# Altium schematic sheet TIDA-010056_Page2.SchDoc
size 431 x 279 mm; Date: Not shown in title block; ApprovedBy: Not shown in title block; CheckedBy: Not shown in title block; Author: Not shown in title block; CompanyName: Not shown in title block; DrawnBy: Manu; Engineer: Not shown in title block; Organization: Not shown in title block; Address1: Not shown in title block; Address2: Not shown in title block; Address3: Not shown in title block; Address4: Not shown in title block; DocumentNumber: 1; Revision: Use project parameter SCH_Rev; SheetNumber: 3; SheetTotal: 5; PageSetup: Record=PageOptions¦CenterHorizontal=True¦CenterVertical=True¦PrintScale=1.00¦XCorrection=1.00¦YCorrection=1.00¦PrintKind=0¦BorderSize=5000000¦LeftOffset=0¦BottomOffset=0¦Orientation=2¦PaperLength=1000¦PaperWidth=1000¦Scale=100¦PaperSource=15¦PrintQuality=600¦MediaType=1¦DitherType=10¦PaperKind=Letter¦PrintScaleMode=1
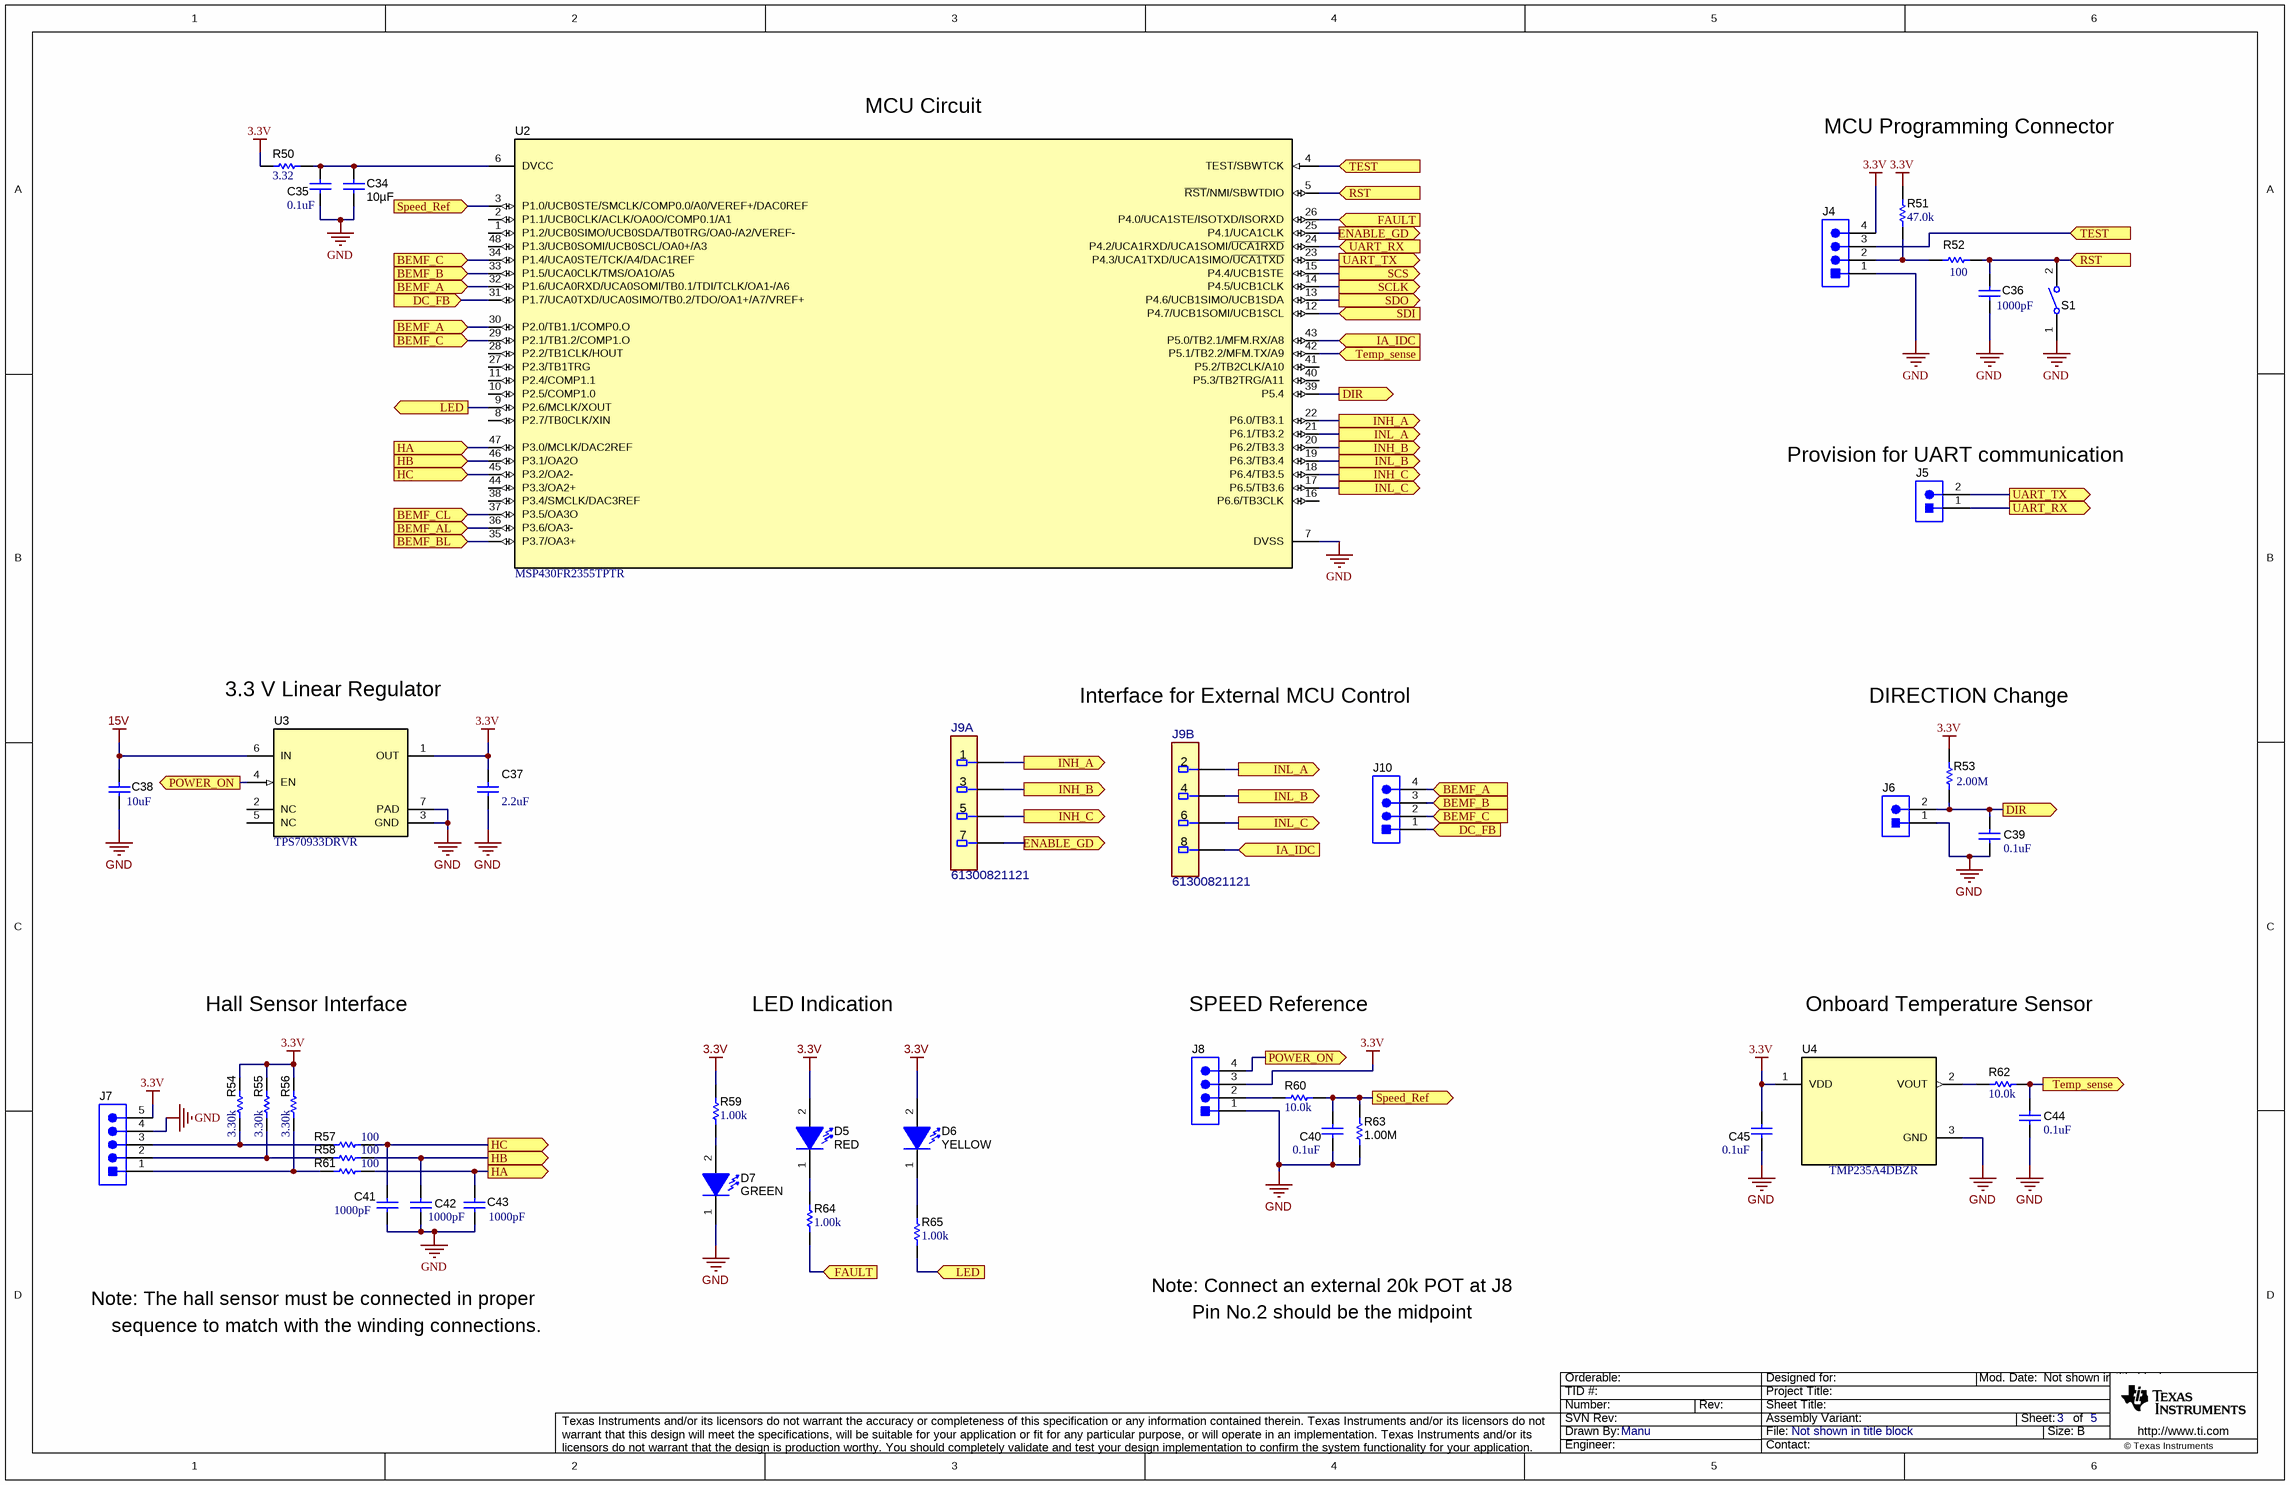
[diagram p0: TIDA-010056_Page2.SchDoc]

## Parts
C34  ValueDisplayed: 10µF  [0603]  (hidden comment: GRM188R61A106KE69D)
C35  ValueDisplayed: 0.1uF  [0402]  (hidden comment: GCM155R71A104KA55D)
C36  ValueDisplayed: 1000pF  [0402]  (hidden comment: GRM155R71C102KA01D)
C37  ValueDisplayed: 2.2uF  [0402]  (hidden comment: 885012105013)
C38  ValueDisplayed: 10uF  [1206_190]  (hidden comment: C3216X7R1V106M160AC)
C39  ValueDisplayed: 0.1uF  [0402]  (hidden comment: GCM155R71A104KA55D)
C40  ValueDisplayed: 0.1uF  [0402]  (hidden comment: GCM155R71A104KA55D)
C41  ValueDisplayed: 1000pF  [0402]  (hidden comment: GRM155R71C102KA01D)
C42  ValueDisplayed: 1000pF  [0402]  (hidden comment: GRM155R71C102KA01D)
C43  ValueDisplayed: 1000pF  [0402]  (hidden comment: GRM155R71C102KA01D)
C44  ValueDisplayed: 0.1uF  [0402]  (hidden comment: GCM155R71A104KA55D)
C45  ValueDisplayed: 0.1uF  [0402]  (hidden comment: GCM155R71A104KA55D)
D5  value RED  [WL-SMCW_GREEN]  (hidden comment: 150060GS75000)
D6  value YELLOW  [WL-SMCW_GREEN]  (hidden comment: 150060GS75000)
D7  value GREEN  [WL-SMCW_GREEN]  (hidden comment: 150060GS75000)
J4  61300411121  [WURTH_61300411121]  (value not drawn)
J5  61300211121  [WURTH_61300211121]  (value not drawn)
J6  61300211121  [WURTH_61300211121]  (value not drawn)
J7  61300511121  [Wurth_61300511121]  (value not drawn)
J8  61300411121  [WURTH_61300411121]  (value not drawn)
J9  61300821121  [FP-61300821121_HDR8-MFG]  (parts A,B of 2)
J10  61300411121  [WURTH_61300411121]  (value not drawn)
R50  ValueDisplayed: 3.32  [0402]  (hidden comment: CRCW04023R32FKED)
R51  ValueDisplayed: 47.0k  [0402]  (hidden comment: RC0402FR-0747KL)
R52  ValueDisplayed: 100  [0402]  (hidden comment: ERJ-2GEJ101X)
R53  ValueDisplayed: 2.00M  [0402]  (hidden comment: CRCW04022M00FKED)
R54  ValueDisplayed: 3.30k  [0402]  (hidden comment: ERJ-2RKF3301X)
R55  ValueDisplayed: 3.30k  [0402]  (hidden comment: ERJ-2RKF3301X)
R56  ValueDisplayed: 3.30k  [0402]  (hidden comment: ERJ-2RKF3301X)
R57  ValueDisplayed: 100  [0402]  (hidden comment: ERJ-2GEJ101X)
R58  ValueDisplayed: 100  [0402]  (hidden comment: ERJ-2GEJ101X)
R59  ValueDisplayed: 1.00k  [0402]  (hidden comment: ERJ-2RKF1001X)
R60  ValueDisplayed: 10.0k  [0402]  (hidden comment: ERJ-2RKF1002X)
R61  ValueDisplayed: 100  [0402]  (hidden comment: ERJ-2GEJ101X)
R62  ValueDisplayed: 10.0k  [0402]  (hidden comment: ERJ-2RKF1002X)
R63  ValueDisplayed: 1.00M  [0402]  (hidden comment: ERJ-2RKF1004X)
R64  ValueDisplayed: 1.00k  [0402]  (hidden comment: ERJ-2RKF1001X)
R65  ValueDisplayed: 1.00k  [0402]  (hidden comment: ERJ-2RKF1001X)
S1  434121025816  [SW_434121025816]  (value not drawn)
U2  MSP430FR2355TPTR  [PT0048A_N]
U3  TPS70933DRVR  [DRV0006A]
U4  TMP235A4DBZR  [DBZ0003A_N]

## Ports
BEMF_A (in), BEMF_AL (in), BEMF_B (in), BEMF_BL (in), BEMF_C (in), BEMF_CL (in), DC_FB (in), DIR (out), ENABLE_GD (out), FAULT (in), HA (in), HA (out), HB (in), HB (out), HC (in), HC (out), IA_IDC (in), INH_A (out), INH_B (out), INH_C (out), INL_A (out), INL_B (out), INL_C (out), LED (in), LED (out), POWER_ON (out), RST (in), SCLK (out), SCS (out), SDI (in), SDO (out), Speed_Ref (in), Speed_Ref (out), Temp_sense (in), Temp_sense (out), TEST (in), UART_RX (in), UART_RX (out), UART_TX (out)

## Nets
3.3V: C37.1 C45.1 D5.2(A) D6.2(A) J4.4 J7.5 J8.3 R50.1 R51.2 R53.2 R54.2 R55.2 R56.2 R59.2 U3.1(OUT) U4.1(VDD)
15V: C38.1 U3.6(IN)
GND: C34.2 C35.2 C36.2 C37.2 C38.2 C39.2 C40.2 C41.2 C42.2 C43.2 C44.2 C45.2 D7.1(K) J4.1 J6.1 J7.4 J8.1 R63.1 S1.1 U2.7(DVSS) U3.3(GND) U3.7(PAD) U4.3(GND)
BEMF_A: J10.4 U2.30(P2.0/TB1.1/COMP0.O) U2.32(P1.6/UCA0RXD/UCA0SOMI/TB0.1/TDI/TCLK/OA1-/A6) ; port BEMF_A
BEMF_AL: U2.36(P3.6/OA3-) ; port BEMF_AL
BEMF_B: J10.3 U2.33(P1.5/UCA0CLK/TMS/OA1O/A5) ; port BEMF_B
BEMF_BL: U2.35(P3.7/OA3+) ; port BEMF_BL
BEMF_C: J10.2 U2.29(P2.1/TB1.2/COMP1.O) U2.34(P1.4/UCA0STE/TCK/A4/DAC1REF) ; port BEMF_C
BEMF_CL: U2.37(P3.5/OA3O) ; port BEMF_CL
DC_FB: J10.1 U2.31(P1.7/UCA0TXD/UCA0SIMO/TB0.2/TDO/OA1+/A7/VREF+) ; port DC_FB
DIR: C39.1 J6.2 R53.1 U2.39(P5.4) ; port DIR
ENABLE_GD: J9.7 U2.25(P4.1/UCA1CLK) ; port ENABLE_GD
FAULT: R64.1 U2.26(P4.0/UCA1STE/ISOTXD/ISORXD) ; port FAULT
HA: C43.1 R61.2 U2.47(P3.0/MCLK/DAC2REF) ; port HA
HB: C42.1 R58.2 U2.46(P3.1/OA2O) ; port HB
HC: C41.1 R57.2 U2.45(P3.2/OA2-) ; port HC
IA_IDC: J9.8 U2.43(P5.0/TB2.1/MFM.RX/A8) ; port IA_IDC
INH_A: J9.1 U2.22(P6.0/TB3.1) ; port INH_A
INH_B: J9.3 U2.20(P6.2/TB3.3) ; port INH_B
INH_C: J9.5 U2.18(P6.4/TB3.5) ; port INH_C
INL_A: J9.2 U2.21(P6.1/TB3.2) ; port INL_A
INL_B: J9.4 U2.19(P6.3/TB3.4) ; port INL_B
INL_C: J9.6 U2.17(P6.5/TB3.6) ; port INL_C
LED: R65.1 U2.9(P2.6/MCLK/XOUT) ; port LED
POWER_ON: J8.4 U3.4(EN) ; port POWER_ON
RST: C36.1 R52.2 S1.2 U2.5(~{RST}/NMI/SBWTDIO) ; port RST
SCLK: U2.14(P4.5/UCB1CLK) ; port SCLK
SCS: U2.15(P4.4/UCB1STE) ; port SCS
SDI: U2.12(P4.7/UCB1SOMI/UCB1SCL) ; port SDI
SDO: U2.13(P4.6/UCB1SIMO/UCB1SDA) ; port SDO
Speed_Ref: C40.1 R60.1 R63.2 U2.3(P1.0/UCB0STE/SMCLK/COMP0.0/A0/VEREF+/DAC0REF) ; port Speed_Ref
Temp_sense: C44.1 R62.1 U2.42(P5.1/TB2.2/MFM.TX/A9) ; port Temp_sense
TEST: J4.3 U2.4(TEST/SBWTCK) ; port TEST
UART_RX: J5.1 U2.24(P4.2/UCA1RXD/UCA1SOMI/~{UCA1RXD}) ; port UART_RX
UART_TX: J5.2 U2.23(P4.3/UCA1TXD/UCA1SIMO/~{UCA1TXD}) ; port UART_TX
NetC34_1: C34.1 C35.1 R50.2 U2.6(DVCC)
NetD5_1: D5.1(K) R64.2
NetD6_1: D6.1(K) R65.2
NetD7_2: D7.2(A) R59.1
NetJ4_2: J4.2 R51.1 R52.1
NetJ7_1: J7.1 R56.1 R61.1
NetJ7_2: J7.2 R55.1 R58.1
NetJ7_3: J7.3 R54.1 R57.1
NetJ8_2: J8.2 R60.2
NetR62_2: R62.2 U4.2(VOUT)

Not connected (* = marked no-connect by the designer): U2 1(P1.2/UCB0SIMO/UCB0SDA/TB0TRG/OA0-/A2/VEREF-) 2(P1.1/UCB0CLK/ACLK/OA0O/COMP0.1/A1) 8(P2.7/TB0CLK/XIN) 10(P2.5/COMP1.0) 11(P2.4/COMP1.1) 16(P6.6/TB3CLK) 27(P2.3/TB1TRG) 28(P2.2/TB1CLK/HOUT) 38(P3.4/SMCLK/DAC3REF) 40(P5.3/TB2TRG/A11) 41(P5.2/TB2CLK/A10) 44(P3.3/OA2+) 48(P1.3/UCB0SOMI/UCB0SCL/OA0+/A3); U3 2(NC) 5(NC)

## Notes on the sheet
- (near U2) MCU Circuit
- MCU Programming Connector
- (near J5) Provision for UART communication
- 3.3 V Linear Regulator
- Interface for External MCU Control
- DIRECTION Change
- Hall Sensor Interface
- LED Indication
- SPEED Reference
- Onboard Temperature Sensor
- Note: The hall sensor must be connected in proper
- Note: Connect an external 20k POT at J8
- sequence to match with the winding connections.
- Pin No.2 should be the midpoint

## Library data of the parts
C34 = CMP-0085855-1: CAP, CERM, 10 µF, 10 V,+/- 10%, X5R, 0603; Manufacturer: MuRata; SizeX_mm: 1.6; Value2: 10V; SizeAreaWB_mm2: 4.68; Green_REACh: Incomplete; AEC Category: Q200; SizeArea_mm2: 1.28; SizeY_mm: 0.8; Green_Lifecycle: Active; TaMax_C: 85°C; Value: 10uF; U/M: EA; Polarized: N; TaMin_C: -55°C; SizeZ_mm: 1
C35 C39 C40 C44 C45 = CMP-0006350-2: CAP, CERM, 0.1 uF, 10 V, +/- 10%, X7R, AEC-Q200 Grade 1, 0402; Manufacturer: MuRata; TaMin_C: -55°C; Polarized: N; SizeAreaWB_mm2: 3; Value1: Unknown; U/M: EA; Value: 0.1uF; TaMax_C: 125°C; SizeZ_mm: 0.6; SizeX_mm: 1; SizeY_mm: 0.5; Value2: 10V; AEC Qualified: Y; Cap_F: 100nF; AEC Category: Q200
C36 C41-C43 = CMP-0006638-2: CAP, CERM, 1000 pF, 16 V, +/- 10%, X7R, 0402; Manufacturer: MuRata; TaMin_C: -55°C; Polarized: N; SizeAreaWB_mm2: 3; Value1: Unknown; U/M: EA; Value: 1000pF; TaMax_C: 125°C; SizeZ_mm: 0.6; SizeX_mm: 1; SizeY_mm: 0.5; Value2: 16V; Cap_F: 1nF; AEC Category: Q200
C37 = CMP-0006222-2: CAP, CERM, 2.2 uF, 10 V, +/- 20%, X5R, 0402; Manufacturer: Wurth Elektronik; TaMin_C: -55°C; Polarized: N; SizeAreaWB_mm2: 3; Value1: Unknown; U/M: EA; Value: 2.2uF; TaMax_C: 85°C; SizeZ_mm: 0.6; SizeX_mm: 1; SizeY_mm: 0.5; Value2: 10V; Cap_F: 2.2µF; AEC Category: Q200
C38 = CMP-0008706-2: CAP, CERM, 10 uF, 35 V, +/- 20%, X7R, 1206_190; Manufacturer: TDK; TaMin_C: -55°C; Polarized: N; SizeAreaWB_mm2: 10.92; Value1: Unknown; U/M: EA; Value: 10uF; TaMax_C: 125°C; SizeZ_mm: 1.9; SizeX_mm: 3.2; SizeY_mm: 1.6; Cap_Case: 1206; Value2: 35V; SizeArea_mm2: 5.12; Cap_F: 10µF; AEC Category: Q200
D5 = 150060GS75000: LED RED CLEAR 0603 SMD; Manufacturer: Wurth Elektronics Inc; PartNumber: 150060RS75000; Type: InGaN; Vf_V: 3.2; Value2: 2V; Io_A: 0.02; Tjmax_C: 85; Value1: W; Angle: 140; U/M: EA
D6 = 150060GS75000: LED YELLOW CLEAR 0603 SMD; Manufacturer: Wurth Elektronics Inc; PartNumber: 150060YS75000; Type: InGaN; Vf_V: 2V; Io_A: 0.02; Tjmax_C: 85; Value1: W; Angle: 140; U/M: EA
D7 = 150060GS75000: LED, Green, SMD; Manufacturer: Wurth Elektronics Inc; Type: InGaN; Vf_V: 3.2; Value2: 3.2V; Io_A: 0.02; Tjmax_C: 85; Value1: W; Angle: 140; U/M: EA
J4 J8 J10 = CMP-0054798-2: Header, 2.54 mm, 4x1, Gold, TH; Manufacturer: Wurth Elektronik; Pitch_mm: 2.54; Gender: Male; Row_Count: 1; Cert_UL: Y; Shrouded: N
J5 J6 = CMP-0054794-2: Header, 2.54 mm, 2x1, Gold, TH; Manufacturer: Wurth Elektronik; Shrouded: N; Gender: Male; Green_REACh: Passed; Pitch_mm: 2.54; Green_Lifecycle: Active; Row_Count: 1; Cert_UL: Y
J7 = CMP-0084909-1: Header, 2.54mm, 5x1, Gold, TH; Manufacturer: Wurth Elektronik; Pitch_mm: 2.54; Gender: Male; Row_Count: 1; Shrouded: N; Current_A: 3A; Voltage_V: 250V
J9 = CMP-0087153-1: CONN HEADER VERT 8POS 2.54MM; Manufacturer: Wurth Electronics; Voltage_V: 250V; Row_Count: 2; Current_A: 3A; ContactFinish: Gold
R50 = CMP-0026357-2: RES, 3.32, 1%, 0.063 W, AEC-Q200 Grade 0, 0402; Manufacturer: Vishay-Dale; Power_W: 63mW; TempCo: 100 ppm/C; Value_Code: 3R32; Value: 3.32; SizeX_mm: 1; SizeY_mm: 0.5; SizeZ_mm: 0.6; Value2: 0.063W; AEC Qualified: Y; EIA_Code: E96; VDC_V: 50V; AEC Category: Q200; AEC Grade: 0
R51 = CMP-0026737-1: RES, 47.0 k, 1%, 0.0625 W, 0402; Manufacturer: Yageo America; Power_W: 62.5mW; TempCo: 100 ppm/C; Value_Code: 47k0; U/M: EA; Value: 47.0k; Res_ohm: 47k; SizeX_mm: 1; SizeY_mm: 0.5; SizeZ_mm: 0.6; AEC Qualified: N; VDC_V: 50V; AEC Category: Q200
R52 R57 R58 R61 = CMP-0026993-2: RES, 100, 5%, 0.1 W, AEC-Q200 Grade 0, 0402; Manufacturer: Panasonic; Power_W: 100mW; TempCo: 200 ppm/C; Value_Code: 100R; U/M: EA; Value: 100; EIA_Code: E24; SizeX_mm: 1; SizeY_mm: 0.5; SizeZ_mm: 0.6; Value2: 0.1W; AEC Qualified: Y; AEC Grade: 0; AEC Category: Q200
R53 = CMP-0026245-2: RES, 2.00 M, 1%, 0.063 W, AEC-Q200 Grade 0, 0402; Manufacturer: Vishay-Dale; Power_W: 63mW; TempCo: 100 ppm/C; Value_Code: 2M00; Value: 2.00Meg; EIA_Code: E96; Res_ohm: 2M; SizeX_mm: 1; SizeY_mm: 0.5; SizeZ_mm: 0.6; Value2: 0.063W; AEC Qualified: Y; VDC_V: 50V; AEC Category: Q200; AEC Grade: 0
R54-R56 = CMP-0026695-1: RES, 3.30 k, 1%, 0.1 W, AEC-Q200 Grade 0, 0402; Manufacturer: Panasonic; Power_W: 100mW; TempCo: 100 ppm/C; Value_Code: 3k30; U/M: EA; Value: 3.30k; Res_ohm: 3.3k; SizeX_mm: 1; SizeY_mm: 0.5; SizeZ_mm: 0.6; Value2: 0.1W; AEC Qualified: Y; VDC_V: 50V; AEC Grade: 0; AEC Category: Q200
R59 R64 R65 = CMP-0026657-1: RES, 1.00 k, 1%, 0.1 W, 0402; Manufacturer: Panasonic; Power_W: 100mW; TempCo: 100 ppm/C; Value_Code: 1k00; U/M: EA; Value: 1.00k; EIA_Code: E96; Res_ohm: 1k; SizeX_mm: 1; SizeY_mm: 0.5; SizeZ_mm: 0.6; Value2: 0.1W; VDC_V: 50V; AEC Category: Q200
R60 R62 = CMP-0026658-1: RES, 10.0 k, 1%, 0.1 W, 0402; Manufacturer: Panasonic; Power_W: 100mW; TempCo: 100 ppm/C; Value_Code: 10k0; U/M: EA; Value: 10.0k; EIA_Code: E96; Res_ohm: 10k; SizeX_mm: 1; SizeY_mm: 0.5; SizeZ_mm: 0.6; Value2: 0.1W; VDC_V: 50V; AEC Category: Q200
R63 = CMP-0026660-1: RES, 1.00 M, 1%, 0.1 W, 0402; Manufacturer: Panasonic; Power_W: 100mW; TempCo: 100 ppm/C; Value_Code: 1M00; U/M: EA; Value: 1.00Meg; EIA_Code: E96; Res_ohm: 1M; SizeX_mm: 1; SizeY_mm: 0.5; SizeZ_mm: 0.6; Value2: 0.1W; VDC_V: 50V; AEC Category: Q200
S1 = CMP-0002196-1: Switch, Tactile, SPST, 12 V, SMD; Manufacturer: Wurth Elektronik; CurrentRating_mA: 50A; PositionCount: 1; VDC_V: 12V; SwitchFunction: Off-On
U2 = CMP-0013603-2: Mixed-Signal Microcontroller, PT0048A (LQFP-48); Manufacturer: Texas Instruments; SizeX_mm: 9; CompType: IC; SizeZ_mm: 1.6; SizeArea_mm2: 81; SizeAreaWB_mm2: 121; U/M: EA
U3 = CMP-0066782-1: 150-mA, 30-V, Ultra-Low IQ, Wide Input Low-Dropout Regulator with Reverse Current Protection, DRV0006A (WSON-6); Alternate PartNumber: TPS70933DRVT; Alternate Manufacturer: Texas Instruments; Green_Lifecycle: Active; SizeAreaWB_mm2: 9.0; Green_REACh: Passed; U/M: EA; SizeZ_mm: 0.8; SizeX_mm: 2.0; SizeArea_mm2: 4.0; CompType: IC
U4 = CMP-0013240-1: TMP235A4DBZR, DBZ0003A (SOP-3); Manufacturer: Texas Instruments; SizeZ_mm: 1.12; SizeX_mm: 2.5; SizeY_mm: 3; SizeArea_mm2: 7.5; CompType: IC; U/M: EA; SizeAreaWB_mm2: 14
